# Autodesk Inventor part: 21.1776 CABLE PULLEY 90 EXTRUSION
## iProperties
Created: 2007-05
Part Number: 21.1776 CABLE PULLEY 90 EXTRUSION
Material: Aluminum-6061
Document SubType Name: Modeling
Designer: Andy Moles
Density: 2.71 g/cm^3
Mass: 480.367 g
Surface Area: 1120.22 cm^2
Volume: 177.257 cm^3
Author: Andy Moles
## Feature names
1. Extrusion1
2. Extrusion2
3. Extrusion3
